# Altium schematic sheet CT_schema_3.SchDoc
size 313 x 200 mm
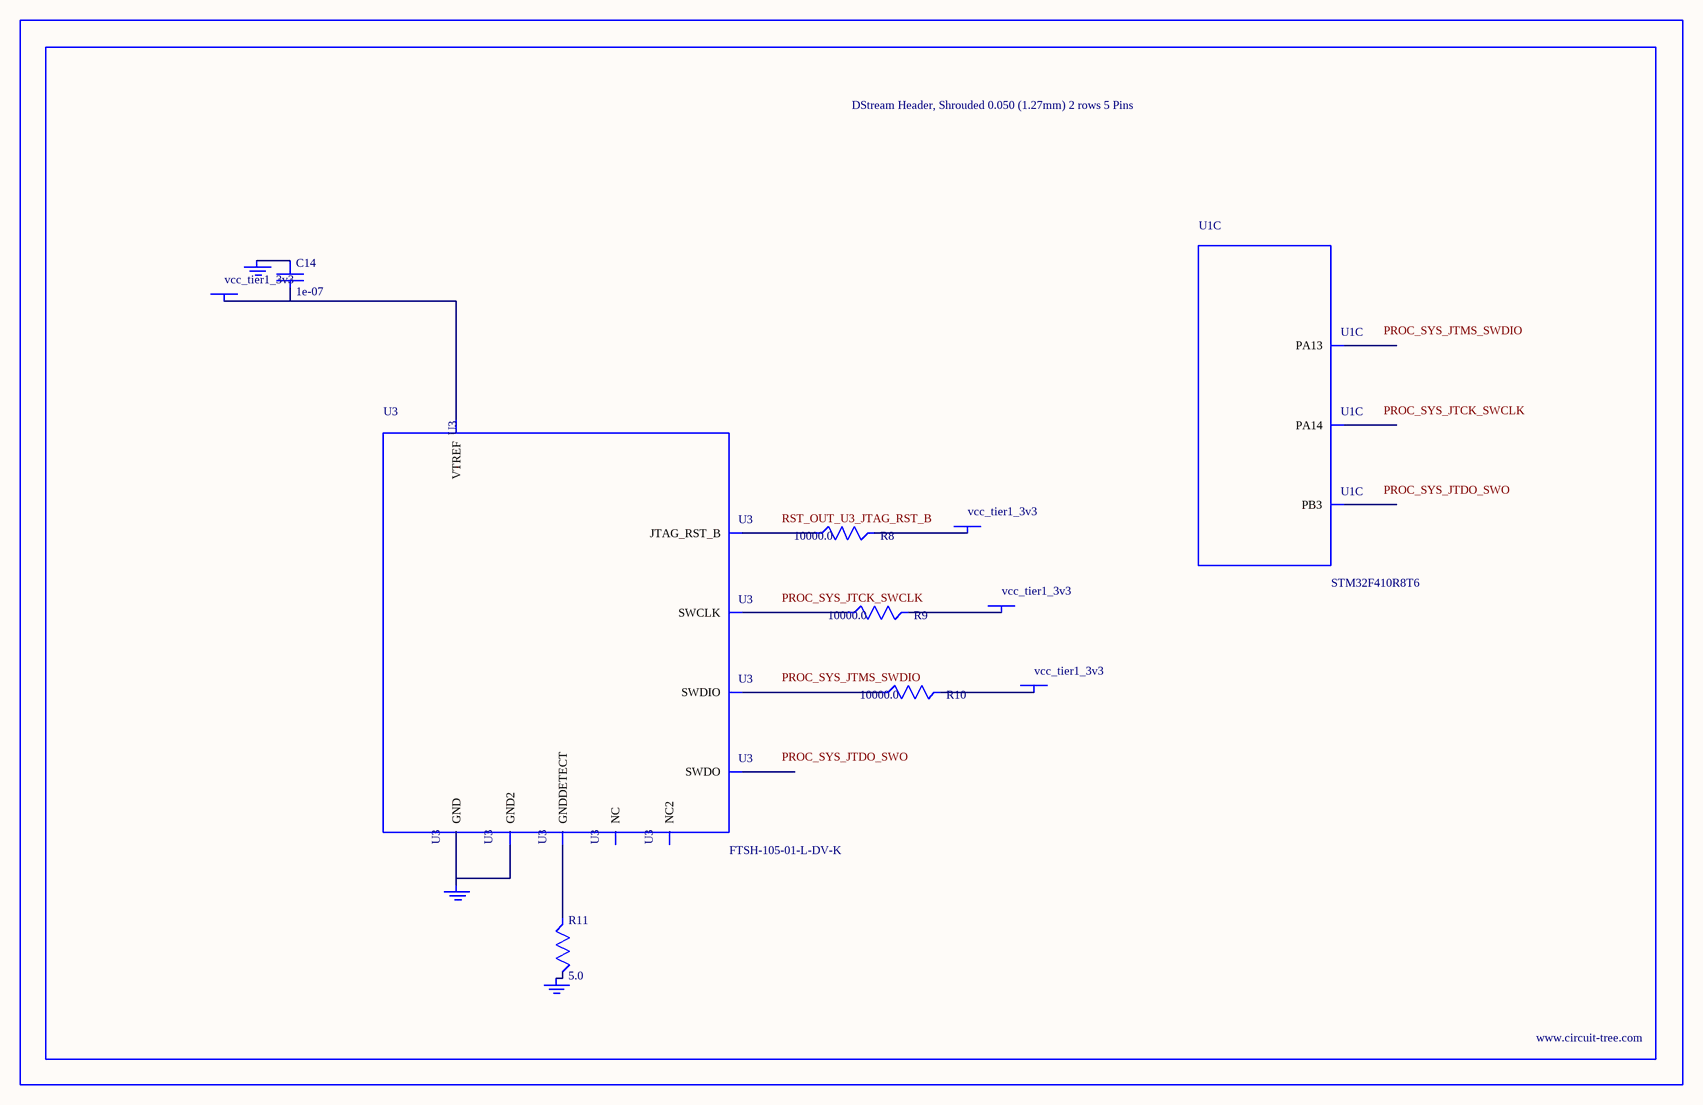
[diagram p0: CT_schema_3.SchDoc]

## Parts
BORDER2  (no value)
C14  1e-07  [C0402]
GND_INSTANCE_2_0  (no value)
GND_INSTANCE_2_1  (no value)
GND_INSTANCE_2_2  (no value)
POWER_INSTANCE_2_0  vcc_tier1_3v3
POWER_INSTANCE_2_1  vcc_tier1_3v3
POWER_INSTANCE_2_2  vcc_tier1_3v3
POWER_INSTANCE_2_3  vcc_tier1_3v3
R8  10000.0  [R0603]
R9  10000.0  [R0603]
R10  10000.0  [R0603]
R11  5.0  [R0603]
U1  STM32F410R8T6  [LQFP64]  (part C of 5)
U3  FTSH-105-01-L-DV-K  [SAMTEC_FTSH-105-01-L-DV-K]

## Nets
NetC14_1: C14.1 GND_INSTANCE_2_0.0(GND)
NetC14_2: C14.2 POWER_INSTANCE_2_0.0(PWR) U3.1(VTREF)
NetGND_INSTANCE_2_1_0: GND_INSTANCE_2_1.0(GND) R11.2
NetGND_INSTANCE_2_2_0: GND_INSTANCE_2_2.0(GND) U3.3(GND) U3.5(GND2)
NetPOWER_INSTANCE_2_1_0: POWER_INSTANCE_2_1.0(PWR) R10.2
NetPOWER_INSTANCE_2_2_0: POWER_INSTANCE_2_2.0(PWR) R9.2
NetPOWER_INSTANCE_2_3_0: POWER_INSTANCE_2_3.0(PWR) R8.2
NetR8_1: R8.1 U3.10(JTAG_RST_B)
NetR9_1: R9.1 U3.4(SWCLK)
NetR10_1: R10.1 U3.2(SWDIO)
NetR11_1: R11.1 U3.9(GNDDETECT)

Not connected (* = marked no-connect by the designer): U1 46(PA13) 49(PA14) 55(PB3); U3 6(SWDO) 7(NC) 8(NC2)

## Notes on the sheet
- Labels drawn without touching a wire or pin: PROC_SYS_JTCK_SWCLK, PROC_SYS_JTDO_SWO, PROC_SYS_JTMS_SWDIO, RST_OUT_U3_JTAG_RST_B

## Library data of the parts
BORDER2 = BORDER_PAGE2
C14 = C0402C104K3RACTU
GND_INSTANCE_2_0-GND_INSTANCE_2_2 = GND
POWER_INSTANCE_2_0-POWER_INSTANCE_2_3 = PWR
R8-R10 = RC0603JR-0710KL
R11 = ERJ-3GEYJ5R1V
